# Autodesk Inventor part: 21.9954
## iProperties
Created: 2009-07
Part Number: 21.9954
Document SubType Name: Modeling
Designer: Administrator
Density: 7.85 g/cm^3
Material: Steel
Mass: 3.32078 g
Surface Area: 6.63172 cm^2
Volume: 0.42303 cm^3
Description: M5x16 Button Head Flange Screw
Translation Standard: STEP AP203
FileName: 92137A420.step
PreProcessor: SolidWorks 2006233
PostProcessor: Build: 236a, Release: 2009 RTM - Date: Fri 02/22/2008
Sent Units: MM
Uncertainty: 1e-05
Author: Administrator
Title: M5x16 Button Head Flange Screw
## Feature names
1. Base1
